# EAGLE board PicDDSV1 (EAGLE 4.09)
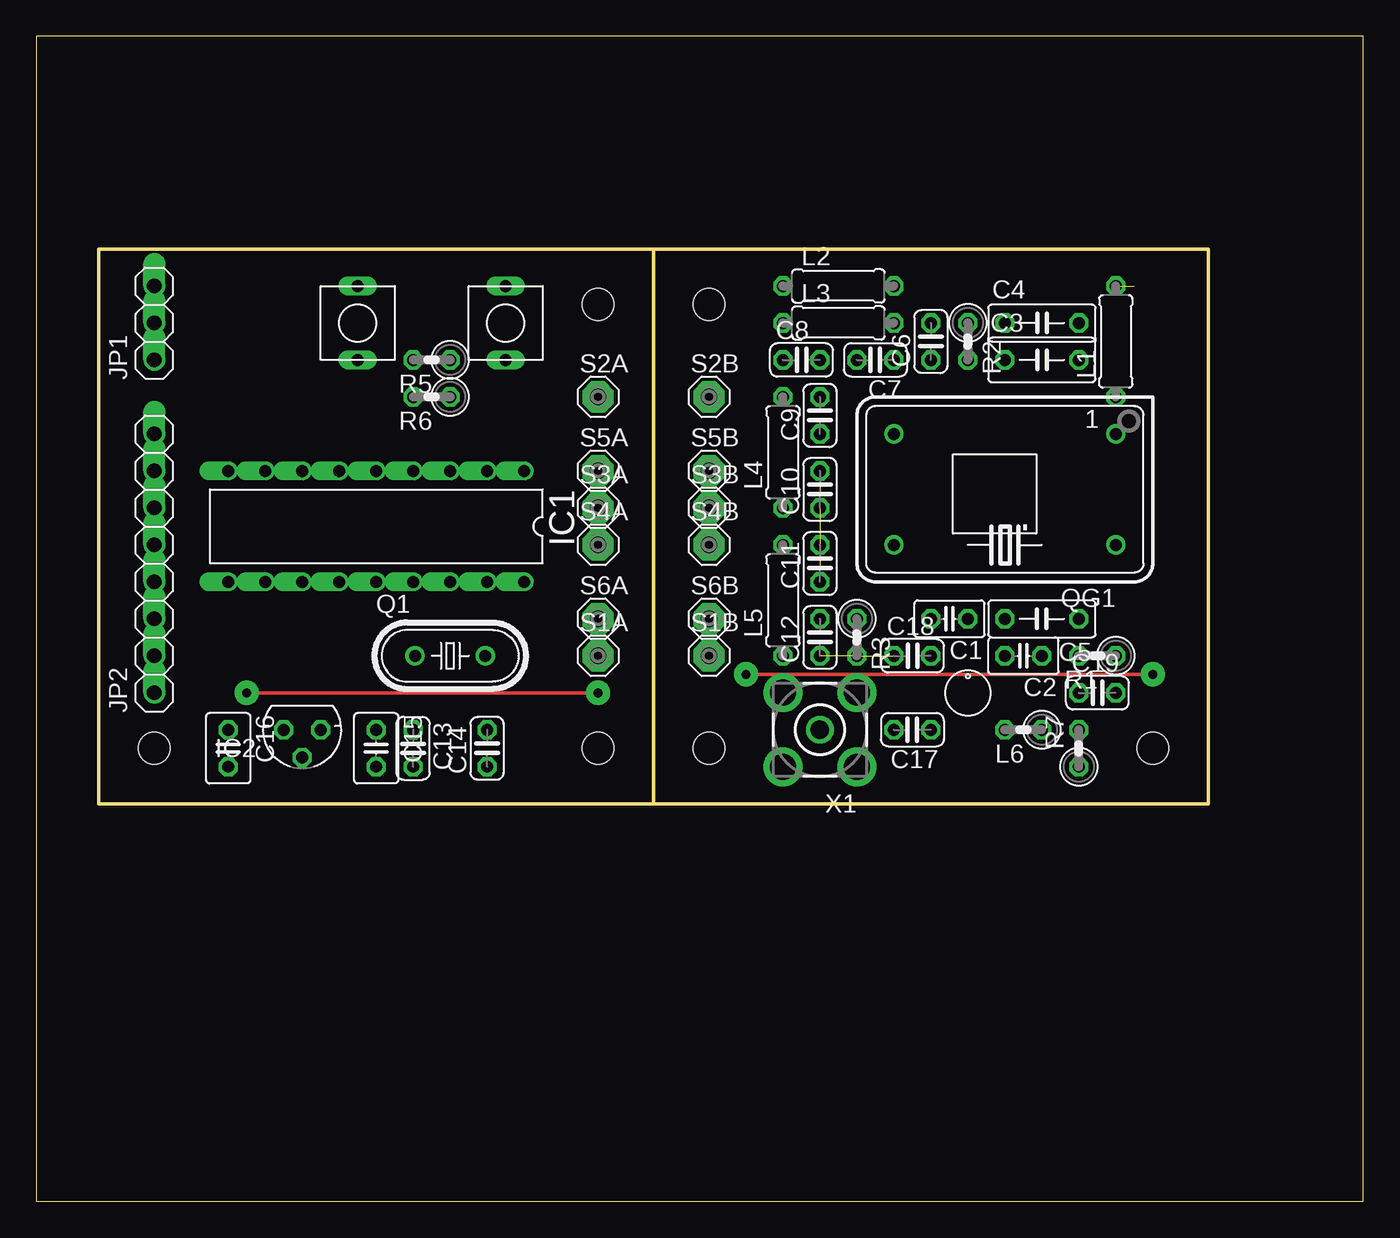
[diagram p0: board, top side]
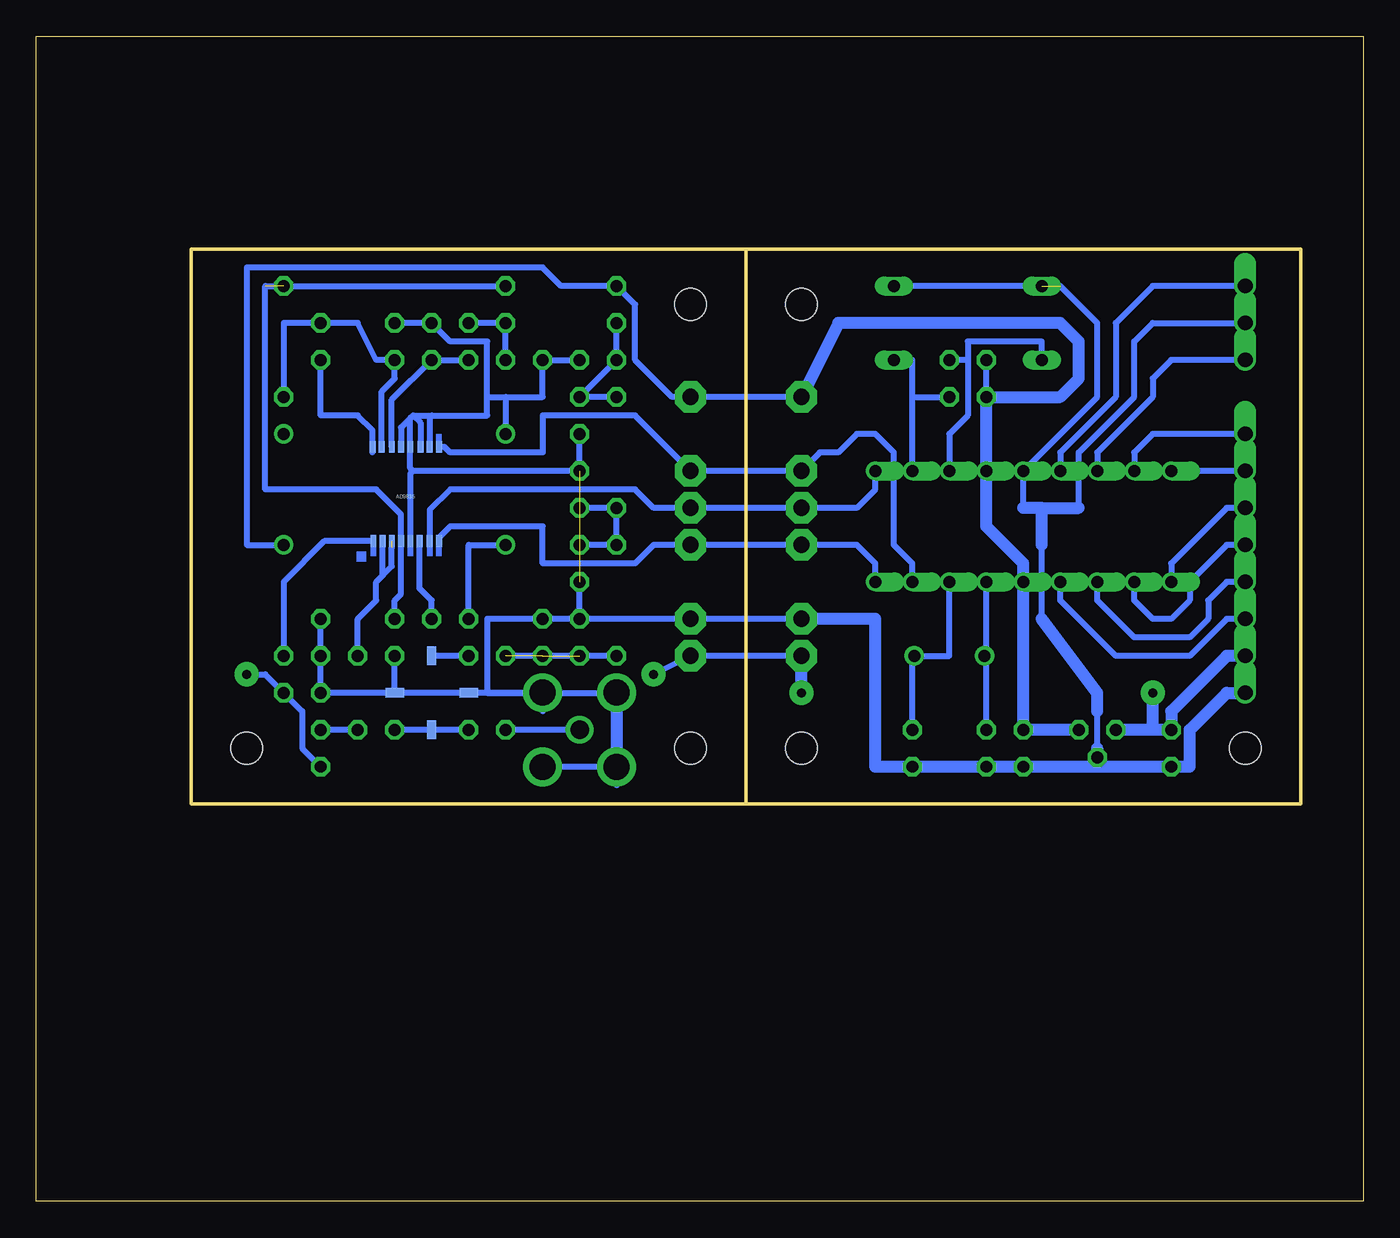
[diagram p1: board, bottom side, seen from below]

Size 91.11 x 80 mm. Coordinates in mm from the lower left corner, seen from the top.
Outline: 42.38,27.3 4.28,27.3 4.28,65.4 42.38,65.4
Outline: 42.38,27.3 80.48,27.3 80.48,65.4 42.38,65.4
Outline: 42.38,27.3 42.38,65.4
Outline: 0,0 91.11,0 91.11,80 0,80 0,0
Copper layers used: Top, Bottom
Holes 2.18 mm at 38.57,61.59 46.19,61.59 46.19,31.11 38.57,31.11 76.67,31.11 8.09,31.11

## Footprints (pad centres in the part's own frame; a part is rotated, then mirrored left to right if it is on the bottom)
C025-025X050 = drill 0.813 octagon: 1 -1.27,0; 2 1.27,0
C050-030X075 = drill 0.813 octagon: 1 -2.54,0; 2 2.54,0
C050-025X075 = drill 0.813 octagon: 1 -2.54,0; 2 2.54,0
C025-024X044 = drill 0.813 octagon: 1 -1.27,0; 2 1.27,0
C025-030X050 = drill 0.813 octagon: 1 -1.27,0; 2 1.27,0
DIL18 = drill 0.813 offset: 1 -10.16,-3.81; 2 -7.62,-3.81; 3 -5.08,-3.81; 4 -2.54,-3.81; 5 0,-3.81; 6 2.54,-3.81; 7 5.08,-3.81; 8 7.62,-3.81; 9 10.16,-3.81; 10 10.16,3.81; 11 7.62,3.81; 12 5.08,3.81; 13 2.54,3.81; 14 0,3.81; 15 -2.54,3.81; 16 -5.08,3.81; 17 -7.62,3.81; 18 -10.16,3.81
78LXX = drill 0.813 octagon: GND 0,1.905; IN 1.27,0; OUT -1.27,0
1X03 = drill 1.016 offset: 1 -2.54,0; 2 0,0; 3 2.54,0
1X08 = drill 1.016 offset: 1 -8.89,0; 2 -6.35,0; 3 -3.81,0; 4 -1.27,0; 5 1.27,0; 6 3.81,0; 7 6.35,0; 8 8.89,0
0207/7 = drill 0.813 octagon: 1 -3.81,0; 2 3.81,0
0207/2V = drill 0.813 octagon: 1 -1.27,0; 2 1.27,0
PMMIC = smd 1.27 x 0.635 bottom: P1 -2.54,0; P3 2.54,0 | smd 0.635 x 1.27 bottom: P2 0,2.54; P4 0,-2.54
HC49U-V = drill 0.813 round: 1 -2.413,0; 2 2.413,0
DIL14S = drill 0.813 round: 1 -7.62,-3.81; 7 7.62,-3.81; 8 7.62,3.81; 14 -7.62,3.81
SE11 = drill 1.118 pad 2.159 octagon: MP 0,0
PBUTTON = drill 0.813 long: P$1 0,2.54; P$2 0,-2.54
TSSOP = smd 0.406 x 0.813 bottom: 1 -1.46,3.556; 2 -0.826,3.556; 3 -0.191,3.556; 4 0.445,3.556; 5 1.079,3.556; 6 1.714,3.556; 7 2.413,3.556; 8 3.048,3.556; 9 3.048,-2.921; 10 2.413,-2.921; 11 1.778,-2.921; 12 1.079,-2.921; 13 0.445,-2.921; 14 -0.191,-2.921; 15 -0.889,-2.921; 16 -1.524,-2.921
BU-SMA-V = drill 1.27 round: 1 0,0 | drill 1.778 round: 2 -2.55,2.55; 3 2.55,2.55; 4 2.55,-2.55; 5 -2.55,-2.55

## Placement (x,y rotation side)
C1  1000pf  [C025-025X050]  62.7,40 180 top
C2  10nf  [C025-025X050]  67.78,37.46 180 top
C3  10nF  [C050-030X075]  69.05,57.78 0 top
C4  100nf  [C050-025X075]  69.05,60.32 0 top
C5  100nf  [C050-025X075]  69.05,40 180 top
C6  1nf  [C025-024X044]  61.43,59.05 90 top
C7  68pf  [C025-024X044]  57.62,57.78 180 top
C8  68pF  [C025-024X044]  52.54,57.78 0 top
C9  68pF  [C025-024X044]  53.81,53.97 90 top
C10  68pF  [C025-024X044]  53.81,48.89 90 top
C11  68pF  [C025-024X044]  53.81,43.81 90 top
C12  68pF  [C025-024X044]  53.81,38.73 90 top
C13  22pf  [C025-024X044]  25.87,31.11 270 top
C14  22pf  [C025-024X044]  30.95,31.11 90 top
C15  100nf  [C025-030X050]  23.33,31.11 270 top
C16  100nf  [C025-030X050]  13.17,31.11 270 top
C17  0.1uF  [C025-024X044]  60.16,32.38 180 top
C18  0.1uF  [C025-024X044]  60.16,37.46 0 top
C19  4,7nf  [C025-024X044]  72.86,34.92 0 top
IC1  PIC16F84AP  [DIL18]  23.33,46.35 180 top
IC2  78L05  [78LXX]  18.25,32.38 180 top
JP1  RS232  [1X03]  8.09,60.32 90 top
JP2  [1X08]  8.09,43.81 90 top
L1  100uH  [0207/7]  74.13,59.05 90 top
L2  100uH  [0207/7]  55.08,62.86 0 top
L3  3.2uH  [0207/7]  55.08,60.32 0 top
L4  3.0uH  [0207/7]  51.27,51.43 90 top
L5  3.2uH  [0207/7]  51.27,41.27 90 top
L6  100uH  [0207/2V]  67.78,32.38 180 top
M1  ERA  [PMMIC]  63.97,34.92 270 top
Q1  4Mhz  [HC49U-V]  28.41,37.46 0 top
QG1  50Mhz  [DIL14S]  66.51,48.89 180 top
R1  3.3Ko  [0207/2V]  72.86,37.46 180 top
R2  51  [0207/2V]  63.97,59.05 270 top
R3  50  [0207/2V]  56.35,38.73 270 top
R5  4.7K  [0207/2V]  27.14,57.78 180 top
R6  4.7K  [0207/2V]  27.14,55.24 180 top
R7  110/12V, 66/9V  [0207/2V]  71.59,31.11 90 top
S1A  SE11  [SE11]  38.57,37.46 0 top
S1B  SE11  [SE11]  46.19,37.46 0 top
S2A  SE11  [SE11]  38.57,55.24 0 top
S2B  SE11  [SE11]  46.19,55.24 0 top
S3  BUTTON1  [PBUTTON]  22.06,60.32 180 top
S3A  SE11  [SE11]  38.57,47.62 0 top
S3B  SE11  [SE11]  46.19,47.62 0 top
S4  BUTTON1  [PBUTTON]  32.22,60.32 180 top
S4A  SE11  [SE11]  38.57,45.08 0 top
S4B  SE11  [SE11]  46.19,45.08 0 top
S5A  SE11  [SE11]  38.57,50.16 0 top
S5B  SE11  [SE11]  46.19,50.16 0 top
S6A  SE11  [SE11]  38.57,40 0 top
S6B  SE11  [SE11]  46.19,40 0 top
U$1  AD9835  [TSSOP]  66.51,48.89 180 top
X1  [BU-SMA-V]  53.81,32.38 180 top

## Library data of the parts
C1-C19 L1-L6 R1-R3 R5-R7 = rcl
IC1 = microchip
IC2 = v-reg
JP1 JP2 = pinhead
M1 = Mmic
Q1 QG1 = crystal
S1A S1B S2A S2B S3A S3B S4A S4B S5A S5B S6A S6B = solpad
S3 S4 = Button
U$1 = ad9835
X1 = con-coax

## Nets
GND: C2.2 C4.1 C5.1 C7.2 C8.2 C9.1 C10.2 C11.1 C12.2 C13.2 C14.1 C15.2 C16.2 C19.1 IC1.5 IC2.GND JP1.2 JP2.1 M1.P2 M1.P4 QG1.7 R1.2 R2.1 R3.1 S3.P$2 S4.P$2 S6A.MP S6B.MP U$1.5 U$1.10 U$1.11 U$1.12 U$1.13 X1.2 X1.3 X1.4 X1.5
N$1: C17.1 L6.2 M1.P3
N$2: IC1.17 S5A.MP S5B.MP U$1.9
N$3: C14.2 IC1.16 Q1.2
N$4: C2.1 U$1.2 U$1.3
N$5: C1.1 U$1.6
N$6: C1.2 QG1.8
N$7: C13.1 IC1.15 Q1.1
N$8: R1.1 U$1.1
N$9: C5.2 L1.2 L2.2 U$1.4
N$10: C6.1 R2.2 U$1.14
N$11: C18.2 M1.P1
N$12: C6.2 C7.1 L3.2
N$13: C8.1 C9.2 L3.1 L4.2
N$14: C10.1 C11.2 L4.1 L5.2
N$15: C12.1 C18.1 L5.1 R3.2
N$16: IC1.1 S3A.MP S3B.MP U$1.7
N$17: IC1.7 JP1.1
N$18: IC1.6 JP1.3
N$19: C3.2 U$1.16
N$20: IC1.18 S4A.MP S4B.MP U$1.8
N$21: IC1.3 R5.1 S3.P$1
N$22: IC1.2 R6.1 S4.P$1
N$23: IC1.13 JP2.3
N$24: IC1.12 JP2.4
N$25: IC1.11 JP2.5
N$26: IC1.10 JP2.6
N$27: IC1.9 JP2.7
N$28: IC1.8 JP2.8
N$29: C3.1 C4.2 L1.1 U$1.15
N$32: C17.2 X1.1
N$34: L6.1 R7.2
N$36: C16.1 C19.2 IC2.IN JP2.2 R7.1 S1A.MP S1B.MP
VCC: C15.1 IC1.4 IC1.14 IC2.OUT L2.1 QG1.14 R5.2 R6.2 S2A.MP S2B.MP

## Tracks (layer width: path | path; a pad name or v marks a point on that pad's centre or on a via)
GND  (2 unrouted)
  Bottom 0.406: 19.52,47.62 19.52,51.43 15.71,55.24 15.71,59.05 14.44,60.32 JP1.2 | 23.33,47.62 IC1.5 18.25,55.24 18.25,60.32 20.79,62.86 | C8.2 C7.2 56.35,55.24 58.89,55.24 | C9.1 C10.2 65.24,50.16 | C12.2 C11.1 | C12.2 R3.1 60.16,40 60.16,34.92 X1.5 | X1.5 56.35,33.65 | X1.5 M1.P4 M1.P2 | M1.P2 C19.1 R1.2 C5.1 | X1.3 51.26,28.57 | X1.2 X1.3 51.26,28.57 | 51.26,28.57 X1.4 | X1.5 | X1.5 X1.4 | 65.24,50.16 65.43,50.35 U$1.12 65.43,53.78 65.24,53.97 | U$1.5 65.43,49.97 65.24,50.16 | C4.1 R2.1 62.7,59.05 60.16,59.05 60.16,55.24 | M1.P2 C2.2 | S6A.MP S6B.MP C12.2 | S3.P$2 S4.P$2 | 18.25,31.11 18.25,33.65 | 22.06,40 22.06,45.08 | 58.89,55.24 QG1.7 | 60.16,55.24 58.89,55.24 | 60.16,55.24 60.16,53.97 63.97,53.97 | 65.24,53.97 63.97,53.97 | U$1.10 64.1,53.84 63.97,53.97 | U$1.11 64.73,53.46 65.24,53.97 | U$1.13 66.07,53.14 65.24,53.97
  Bottom 0.813: IC2.GND 18.25,31.11 18.25,29.84 | 18.25,29.84 C15.2 C13.2 C14.1 33.49,29.84 33.49,40 S6A.MP | X1.3 X1.4 | 22.06,47.62 19.52,47.62 | 22.06,47.62 23.33,47.62 | 22.06,45.08 22.06,47.62 | 22.06,40 18.25,34.92 18.25,33.65 | JP2.1 9.36,34.92 11.9,32.38 11.9,29.84 C16.2 18.25,29.84
N$1
  Bottom 0.406: C17.1 M1.P3 L6.2
N$2
  Bottom 0.406: IC1.17 30.95,43.81 32.22,45.08 32.22,51.43 33.49,52.7 34.76,52.7 36.03,51.43 37.3,51.43 S5A.MP S5B.MP 50,53.97 56.35,53.97 56.35,51.43 62.7,51.43 63.08,51.81 U$1.9
N$3
  Bottom 0.406: C14.2 30.95,37.46 | Q1.2 30.82,37.59 30.95,37.46 | 30.95,37.46 28.41,37.46 IC1.16
N$4  (1 unrouted)
  Bottom 0.406: C2.1 69.05,40 67.78,41.27 67.78,42.54 | 66.7,44.89 66.7,43.62 67.78,42.54 | U$1.2 67.33,42.98 67.78,42.54
N$5
  Bottom 0.406: U$1.6 64.8,42.1 63.97,41.27 C1.1
N$6
  Bottom 0.406: QG1.8 61.43,45.08 C1.2
N$7
  Bottom 0.406: 25.87,37.46 Q1.1 | 25.87,37.46 IC1.15 | C13.1 25.87,37.46
N$8
  Bottom 0.406: R1.1 74.13,42.54 71.34,45.33 U$1.1
N$9  (1 unrouted)
  Bottom 0.406: L2.2 75.4,62.86 75.4,48.89 67.78,48.89 66.07,47.18 U$1.4 66.07,41.71 66.51,41.27 C5.2
N$10
  Bottom 0.406: C6.1 R2.2 66.7,55.05 U$1.14
N$11
  Bottom 0.406: C18.2 M1.P1
N$12
  Bottom 0.406: C7.1 L3.2 C6.2
N$13
  Bottom 0.406: L3.1 C8.1 C9.2 L4.2
N$14
  Bottom 0.406: L5.2 L4.1 | L4.1 C10.1 L4.1 | L5.2 L4.1 | L5.2 C11.2
N$15  (2 unrouted)
  Bottom 0.406: L5.1 C18.1
N$16
  Bottom 0.406: IC1.1 33.49,48.89 34.76,47.62 S3A.MP S3B.MP 48.73,47.62 50,48.89 62.7,48.89 64.1,47.49 U$1.7
N$17
  Bottom 0.406: IC1.7 18.25,51.43 14.44,55.24 14.44,56.51 13.17,57.78 JP1.1
N$18
  Bottom 0.406: IC1.6 20.79,51.43 16.98,55.24 16.98,60.32 14.44,62.86 JP1.3
N$19
  Bottom 0.406: 68.03,51.43 U$1.16 68.03,52.95 69.05,53.97 71.59,53.97 C3.2
N$20
  Bottom 0.406: IC1.18 33.49,43.81 34.76,45.08 S4A.MP S4B.MP 48.73,45.08 50,43.81 56.35,43.81 56.35,46.35 62.7,46.35 63.46,45.59 U$1.8
N$21
  Bottom 0.406: IC1.3 28.41,52.7 27.14,53.97 27.14,57.78 | 27.14,57.78 R5.1 | 27.14,57.78 27.14,59.05 22.06,59.05 S3.P$1
N$22
  Bottom 0.406: 30.95,51.43 IC1.2 30.95,55.24 | 30.95,55.24 R6.1 | 30.95,55.24 30.95,57.78 S4.P$1
N$23
  Bottom 0.406: IC1.13 20.79,41.27 16.98,37.46 11.9,37.46 9.36,40 JP2.3
N$24
  Bottom 0.406: IC1.12 18.25,41.27 15.71,38.73 11.9,38.73 10.63,40 10.63,41.27 9.36,42.54 JP2.4
N$25
  Bottom 0.406: IC1.11 15.71,41.27 14.44,40 13.17,40 11.9,41.27 11.9,42.54 9.36,45.08 JP2.5
N$26
  Bottom 0.406: JP2.6 9.36,47.62 13.17,43.81 IC1.10
N$27
  Bottom 0.406: JP2.7 IC1.9
N$28
  Bottom 0.406: IC1.8 15.71,51.43 14.44,52.7 JP2.8
N$29
  Bottom 0.406: L1.1 74.13,60.32 C4.2 69.05,60.32 67.78,57.78 C3.1 66.51,56.51 67.4,55.62 U$1.15
N$30  (via drill 0.61 pad 1.68)
  other vias: 14.44,34.92
N$31  (via drill 0.61 pad 1.68)
  other vias: 76.67,36.19
N$32
  Bottom 0.406: X1.1 C17.2
N$33  (via drill 0.61 pad 1.68)
  other vias: 48.73,36.19
N$34
  Bottom 0.406: L6.1 R7.2
N$36  (via drill 0.61 pad 1.68)
  Top 0.254: v14.44,34.92 v38.57,34.92 | v48.73,36.19 v76.67,36.19
  Bottom 0.406: S1A.MP S1B.MP v48.73,36.19 | v76.67,36.19 75.4,36.19 C19.2 72.86,33.65 72.86,31.11 R7.1
  Bottom 0.813: 14.44,32.38 IC2.IN | v38.57,34.92 S1A.MP | JP2.2 9.36,37.46 13.17,33.65 C16.1 14.44,32.38 | 14.44,32.38 v14.44,34.92
VCC
  Bottom 0.406: QG1.14 76.67,45.08 76.67,64.13 56.35,64.13 55.08,62.86 L2.1 50,61.59 50,57.78 47.46,55.24 S2B.MP S2A.MP | R6.2 R5.2 R6.2
  Bottom 0.813: IC2.OUT C15.1 IC1.14 23.33,43.81 25.87,46.35 IC1.4 R6.2 20.79,55.24 19.52,56.51 19.52,59.05 20.79,60.32 36.03,60.32 S2A.MP
(copper drawn outside any net)
  shapes: Bottom area x6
